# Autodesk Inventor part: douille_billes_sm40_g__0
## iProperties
Shininess: 20.0
Length Units: 11269
Angle Units: 11279
Time Units: 11290
Mass Units: 11283
Length Display Precision: 3
Angle Display Precision: 2
Created: 2005-02
Part Number: douille_billes_sm40_g__0
Material: Par défaut
Document SubType Name: Modélisation
Designer: ytiennot
Density: 0.0
Volumn: 0.0
Area: 0.0
PropertySet Name: Model Information
Control State: 0
Master: False
Checked Out: False
Author: ytiennot
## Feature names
1. Base1
